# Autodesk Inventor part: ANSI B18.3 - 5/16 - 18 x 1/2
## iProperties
Comments: To add or edit properties for Autodesk Inventor files, use iProperties.
Created: 2005-06
Part Number: ANSI B18.3 - 5/16 - 18 x 1/2
Vendor: Autodesk Inc.
Document SubType Name: Modeling
Designer: John Blackburn
Material: Default
Description: Spline Socket Set Screw - Flat Point - UNC (Regular Thread - Inch)
Standard: ANSI B18.3
Alert: To add or edit properties for Autodesk Inventor files, use iProperties.
Control State: 0
Master: False
Checked Out: False
Shininess: 64.0
Length Units: 11272
Angle Units: 11279
Time Units: 11290
Mass Units: 11286
Length Display Precision: 3
Angle Display Precision: 2
Compacted: True
EGR: 3
Density: 0.0
Volumn: 0.0
Area: 0.0
PropertySet Name: Model Information
Author: John Blackburn
Revision Number: 8
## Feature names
1. Body [Revolution]
2. Slot [Extrusion]
3. Slots [Circular Pattern]
4. Chamfer1
5. Chamfer2
